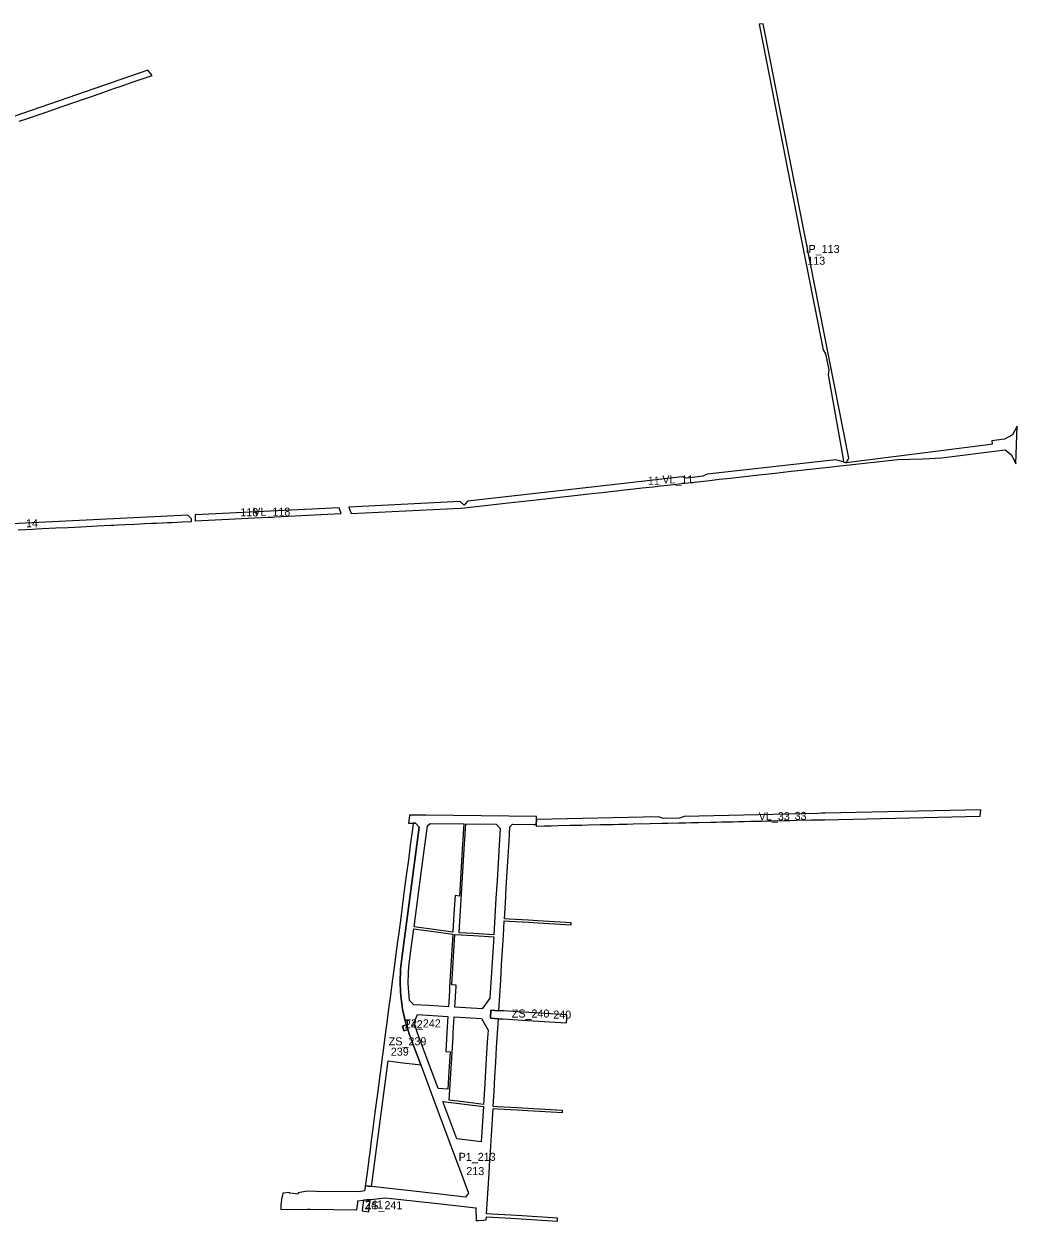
# Model space of a CAD drawing. Extents: x -521939 to -518034, y -1194984 to -1189555.
# Drawn here: x -519897 to -518662, y -1191480 to -1189991 of the extents above; entities that cross this region are included whole.
import ezdxf

# ---------------------------------------------------------------- set-up
doc = ezdxf.new("R2010")
doc.units = 0
doc.layers.add('96120023', color=7, linetype='Continuous')
doc.layers.add('ID VPS', color=7, linetype='Continuous')

msp = doc.modelspace()

# ---------------------------------------------------------------- linework, layer by layer
at = {"layer": '96120023'}
for points in [[(-518977.46, -1189990.66), (-518982.75, -1189991.08)], [(-518982.75, -1189991.08), (-518973.66, -1190037.25)], [(-518968.46, -1190036.36), (-518977.46, -1189990.66)], [(-518973.66, -1190037.25), (-518966.93, -1190071.42)], [(-518961.73, -1190070.59), (-518968.46, -1190036.36)], [(-519742.92, -1190048.01), (-519787.45, -1190063.39), (-519954.51, -1190121.09), (-519959.21, -1190124.83), (-519978.27, -1190131.41), (-519984.27, -1190131.37), (-520061.95, -1190158.2), (-520231.96, -1190216.92), (-520235.61, -1190223.15)], [(-519762.5, -1190063.2), (-519737.67, -1190054.66)], [(-519737.67, -1190054.66), (-519742.92, -1190048.01)], [(-519802.38, -1190076.99), (-519794.41, -1190074.26)], [(-519794.41, -1190074.26), (-519785.22, -1190071.01)], [(-519785.22, -1190071.01), (-519776.17, -1190067.93)], [(-519776.17, -1190067.93), (-519762.5, -1190063.2)], [(-518966.93, -1190071.42), (-518932.65, -1190245.48), (-518903.01, -1190395.98), (-518899.95, -1190401.14), (-518896.05, -1190420.93), (-518896.92, -1190426.87), (-518880.88, -1190515.41), (-518878.11, -1190531.65)], [(-518871.13, -1190530.87), (-518961.73, -1190070.59)], [(-519849.58, -1190093.29), (-519821.87, -1190083.74)], [(-519821.87, -1190083.74), (-519813.04, -1190080.72)], [(-519813.04, -1190080.72), (-519802.38, -1190076.99)], [(-519893.94, -1190108.6), (-519871.89, -1190101.04)], [(-519871.89, -1190101.04), (-519862.6, -1190097.78)], [(-519862.6, -1190097.78), (-519849.58, -1190093.29)], [(-519903.02, -1190111.63), (-519893.94, -1190108.6)], [(-518661.8, -1190490.82), (-518667.64, -1190501.77), (-518677.22, -1190507.17), (-518693.26, -1190509.28)], [(-518663.34, -1190537.95), (-518661.8, -1190490.82)], [(-518693.26, -1190509.28), (-518692.74, -1190513.36), (-518697.59, -1190513.92), (-518874.29, -1190536.33)], [(-518810.26, -1190532.19), (-518779.08, -1190531.51), (-518755.65, -1190530.1), (-518676.76, -1190520.2), (-518668.57, -1190526.63), (-518663.34, -1190537.95)], [(-518887.27, -1190532.68), (-519047.1, -1190550.59), (-519052.5, -1190553.21), (-519072.55, -1190555.45), (-519078.39, -1190554.09), (-519168.97, -1190564.24), (-519345.4, -1190584.01), (-519349.64, -1190589.23)], [(-518884.52, -1190533.45), (-518887.27, -1190532.68)], [(-518877.94, -1190535.3), (-518884.52, -1190533.45)], [(-518878.11, -1190531.65), (-518877.94, -1190535.3)], [(-518877.94, -1190535.3), (-518874.29, -1190536.33)], [(-518874.29, -1190536.33), (-518877.94, -1190535.3)], [(-518877.74, -1190539.66), (-518810.26, -1190532.19)], [(-518874.29, -1190536.33), (-518871.13, -1190530.87)], [(-518983.05, -1190551.46), (-518962.5, -1190549.15)], [(-518962.5, -1190549.15), (-518942.66, -1190546.94)], [(-518942.66, -1190546.94), (-518930.55, -1190545.57)], [(-518930.55, -1190545.57), (-518919.4, -1190544.34)], [(-518919.4, -1190544.34), (-518899.77, -1190542.15)], [(-518899.77, -1190542.15), (-518882.35, -1190540.18)], [(-518882.35, -1190540.18), (-518877.74, -1190539.66)], [(-519114.47, -1190566.26), (-519105.69, -1190565.24)], [(-519105.69, -1190565.24), (-519096.49, -1190564.2)], [(-519096.49, -1190564.2), (-519078.49, -1190562.26)], [(-519078.49, -1190562.26), (-519051.92, -1190559.12)], [(-519051.92, -1190559.12), (-519044.06, -1190558.34)], [(-519044.06, -1190558.34), (-519032.44, -1190556.99)], [(-519032.44, -1190556.99), (-519018.45, -1190555.44)], [(-519018.45, -1190555.44), (-519008.01, -1190554.21)], [(-519008.01, -1190554.21), (-518993.5, -1190552.64)], [(-518993.5, -1190552.64), (-518983.05, -1190551.46)], [(-519244.88, -1190580.73), (-519230.8, -1190579.2)], [(-519230.8, -1190579.2), (-519212.48, -1190577.18)], [(-519212.48, -1190577.18), (-519194.65, -1190575.18)], [(-519194.65, -1190575.18), (-519178.48, -1190573.43)], [(-519178.48, -1190573.43), (-519159.93, -1190571.22)], [(-519159.93, -1190571.22), (-519150.74, -1190570.16)], [(-519150.74, -1190570.16), (-519138.65, -1190568.93)], [(-519138.65, -1190568.93), (-519128.12, -1190567.71)], [(-519128.12, -1190567.71), (-519114.47, -1190566.26)], [(-519505.17, -1190592.27), (-519684.06, -1190601.07)], [(-519502.67, -1190599.7), (-519505.17, -1190592.27)], [(-519354.59, -1190584.65), (-519492.88, -1190591.75)], [(-519492.88, -1190591.75), (-519490.33, -1190599.63)], [(-519490.33, -1190599.63), (-519354.17, -1190593)], [(-519349.64, -1190589.23), (-519354.59, -1190584.65)], [(-519354.17, -1190593), (-519349.34, -1190592.5)], [(-519349.34, -1190592.5), (-519294.71, -1190586.4)], [(-519294.71, -1190586.4), (-519279.13, -1190584.54)], [(-519279.13, -1190584.54), (-519244.88, -1190580.73)], [(-519693.24, -1190601.52), (-519752.34, -1190604.4), (-519929.64, -1190613.04), (-519935.19, -1190615.32), (-519939.78, -1190615.54)], [(-519713.65, -1190610.53), (-519700.36, -1190609.88)], [(-519700.36, -1190609.88), (-519688.65, -1190609.3)], [(-519688.62, -1190605.97), (-519693.24, -1190601.52)], [(-519688.65, -1190609.3), (-519688.62, -1190605.97)], [(-519684.13, -1190608.58), (-519502.67, -1190599.7)], [(-519684.06, -1190601.07), (-519684.13, -1190608.58)], [(-519904.19, -1190619.79), (-519886.32, -1190618.93)], [(-519886.32, -1190618.93), (-519881.51, -1190618.7)], [(-519881.51, -1190618.7), (-519874.3, -1190618.35)], [(-519874.3, -1190618.35), (-519857.39, -1190617.5)], [(-519857.39, -1190617.5), (-519842, -1190616.75)], [(-519842, -1190616.75), (-519826.46, -1190615.97)], [(-519826.46, -1190615.97), (-519806.02, -1190614.98)], [(-519806.02, -1190614.98), (-519789.16, -1190614.2)], [(-519789.16, -1190614.2), (-519785.45, -1190613.97)], [(-519785.45, -1190613.97), (-519780.36, -1190613.76)], [(-519780.36, -1190613.76), (-519770.89, -1190613.31)], [(-519770.89, -1190613.31), (-519759.09, -1190612.73)], [(-519759.09, -1190612.73), (-519746.72, -1190612.13)], [(-519746.72, -1190612.13), (-519738.62, -1190611.73)], [(-519738.62, -1190611.73), (-519732.39, -1190611.44)], [(-519732.39, -1190611.44), (-519725.37, -1190611.1)], [(-519725.37, -1190611.1), (-519719.21, -1190610.77)], [(-519719.21, -1190610.77), (-519713.65, -1190610.53)], [(-519259.67, -1190980.24), (-519259.53, -1190976.44), (-519397.29, -1190974.84), (-519409.21, -1190974.7), (-519417.62, -1190974.6), (-519417.66, -1190974.95), (-519417.58, -1190975.61), (-519417.75, -1190975.6), (-519418.57, -1190981.92), (-519418.92, -1190984.59), (-519412.96, -1190984.66), (-519411.43, -1190984.67), (-519409.91, -1190984.69), (-519405.56, -1190989.71), (-519426.73, -1191149.73), (-519428.73, -1191166.25), (-519429.31, -1191182.88), (-519428.77, -1191193.5), (-519428.47, -1191199.49), (-519426.21, -1191215.98), (-519422.56, -1191232.21)], [(-519259.67, -1190980.24), (-519259.89, -1190986.43)], [(-519259.89, -1190986.43), (-519259.67, -1190980.24)], [(-519210.6, -1190987.17), (-519202.99, -1190986.99), (-519195.39, -1190986.84), (-519180.12, -1190986.51), (-519171.98, -1190986.32), (-519164.58, -1190986.14), (-519157.3, -1190985.98), (-519146.73, -1190985.75), (-519139.45, -1190985.59), (-519118.38, -1190985.11), (-519103.75, -1190984.78), (-519096.18, -1190984.64), (-519082.46, -1190984.32), (-519074.13, -1190984.14), (-519066.62, -1190983.97), (-519057.96, -1190983.78), (-519043.29, -1190983.45), (-519036.25, -1190983.29), (-519029.04, -1190983.14), (-519015.53, -1190982.84), (-519008.2, -1190982.68), (-519001.41, -1190982.5), (-518993.81, -1190982.32), (-518988.21, -1190982.23), (-518979.42, -1190982.05), (-518971.69, -1190981.85), (-518960, -1190981.61), (-518951.6, -1190981.45), (-518943.98, -1190981.24), (-518936.34, -1190981.09), (-518918.12, -1190980.66), (-518905.51, -1190980.41), (-518900.98, -1190980.31), (-518707.73, -1190975.95), (-518706.73, -1190968.01), (-518900.54, -1190972.29), (-518905.06, -1190972.39), (-518909.73, -1190972.5), (-519076.07, -1190976.18), (-519081.68, -1190978.3), (-519101.85, -1190978.75), (-519107.55, -1190976.87), (-519259.67, -1190980.24)], [(-519412.96, -1190984.66), (-519413.94, -1190992.07), (-519416.58, -1191012.09), (-519418.96, -1191030.07), (-519421.56, -1191049.69), (-519424.05, -1191068.52), (-519425.76, -1191081.47), (-519428.51, -1191102.27), (-519430.97, -1191120.9), (-519432.39, -1191131.65), (-519434.43, -1191147.07), (-519436.7, -1191164.25), (-519438.99, -1191181.55), (-519441.23, -1191198.47), (-519443.51, -1191215.75), (-519445.75, -1191232.74), (-519448.07, -1191250.27), (-519450.34, -1191267.46), (-519451.46, -1191275.9), (-519452.43, -1191283.22), (-519454.38, -1191298), (-519457.39, -1191320.76), (-519458.94, -1191332.49), (-519461, -1191348.01), (-519463.15, -1191364.31), (-519465.11, -1191379.15), (-519467.09, -1191394.09), (-519468.15, -1191402.09), (-519468.71, -1191406.36), (-519470.37, -1191418.91), (-519472.32, -1191433.7), (-519472.58, -1191435.69)], [(-519429.31, -1191182.88), (-519428.73, -1191166.25), (-519426.73, -1191149.73), (-519405.56, -1190989.71), (-519409.91, -1190984.69), (-519411.43, -1190984.67), (-519412.96, -1190984.66)], [(-519387.1, -1191117.04), (-519405.94, -1191114.55), (-519411.89, -1191113.76), (-519408.9, -1191091.16), (-519405.91, -1191068.61), (-519403.03, -1191046.8), (-519400.14, -1191024.99), (-519397.25, -1191003.18), (-519395.22, -1190987.84), (-519391.87, -1190984.9), (-519349.98, -1190985.39), (-519350.34, -1190991.38), (-519351.18, -1191005.37), (-519351.49, -1191010.37), (-519355.39, -1191075.29), (-519360.86, -1191074.57), (-519362.23, -1191097.34), (-519363.6, -1191120.15), (-519387.1, -1191117.04)], [(-519337.67, -1191121.99), (-519355.64, -1191120.91), (-519348.98, -1191010.4), (-519348.68, -1191005.4), (-519347.84, -1190991.41), (-519347.48, -1190985.42), (-519309.96, -1190985.85), (-519304.76, -1190991.38), (-519306.01, -1191012.14), (-519307.33, -1191034.1), (-519308.65, -1191056.06), (-519309.98, -1191078.02), (-519311.34, -1191100.73), (-519312.71, -1191123.49), (-519318.7, -1191123.13), (-519337.67, -1191121.99)], [(-519306.37, -1191217.84), (-519305.23, -1191198.83), (-519304.09, -1191179.86), (-519302.94, -1191160.9), (-519301.84, -1191142.63), (-519300.74, -1191124.36), (-519299.64, -1191106.09), (-519293.65, -1191106.46), (-519269.7, -1191107.9), (-519258.03, -1191108.6), (-519216.41, -1191111.11), (-519216.29, -1191108.61), (-519257.89, -1191106.1), (-519269.55, -1191105.4), (-519293.5, -1191103.96), (-519299.49, -1191103.6), (-519298.32, -1191084.03), (-519297.14, -1191064.57), (-519295.97, -1191045.1), (-519294.83, -1191026.14), (-519293.69, -1191007.17), (-519292.6, -1190989.16), (-519289.31, -1190986.09), (-519262.38, -1190986.4), (-519259.89, -1190986.43)], [(-519259.89, -1190986.43), (-519259.96, -1190988.33)], [(-519259.96, -1190988.33), (-519250.24, -1190988.04)], [(-519250.24, -1190988.04), (-519241.28, -1190987.85)], [(-519241.28, -1190987.85), (-519232.69, -1190987.61), (-519218.24, -1190987.34), (-519210.6, -1190987.17)], [(-519387.43, -1191119.47), (-519363.75, -1191122.6), (-519367.7, -1191188.1), (-519368, -1191193.09), (-519368.84, -1191207.07), (-519369.2, -1191213.06), (-519393.15, -1191211.62), (-519412.25, -1191210.47), (-519417.68, -1191205.18), (-519419.26, -1191184.09), (-519418.72, -1191170.93), (-519418.4, -1191162.95), (-519415.36, -1191139.98), (-519412.21, -1191116.19), (-519406.26, -1191116.98), (-519387.43, -1191119.47)], [(-519359.71, -1191188.58), (-519359.57, -1191186.24), (-519365.06, -1191185.91), (-519361.27, -1191123.02), (-519337.82, -1191124.43), (-519318.85, -1191125.58), (-519312.86, -1191125.94), (-519314.75, -1191157.38), (-519316.65, -1191188.82), (-519317.45, -1191202.15), (-519327.17, -1191215.59), (-519361.21, -1191213.54), (-519360.85, -1191207.55), (-519360.01, -1191193.57), (-519359.71, -1191188.58)], [(-519428.77, -1191193.5), (-519429.31, -1191182.88)], [(-519428.47, -1191199.49), (-519428.77, -1191193.5)], [(-519422.56, -1191232.21), (-519426.21, -1191215.98), (-519428.47, -1191199.49)], [(-519316.35, -1191217.24), (-519316.95, -1191227.22)], [(-519316.95, -1191227.22), (-519316.35, -1191217.24)], [(-519306.37, -1191217.84), (-519316.35, -1191217.24)], [(-519316.35, -1191217.24), (-519306.37, -1191217.84)], [(-519276.43, -1191219.64), (-519300.38, -1191218.2), (-519306.37, -1191217.84)], [(-519221.65, -1191222.94), (-519269, -1191220.09), (-519276.43, -1191219.64)], [(-519466.53, -1191452.71), (-519465.48, -1191452.58), (-519448.03, -1191450.51), (-519432.28, -1191452.28), (-519402.01, -1191455.67), (-519374.98, -1191458.69), (-519335.08, -1191463.16), (-519334.48, -1191479.02), (-519333.28, -1191478.93), (-519332.56, -1191478.87), (-519331.7, -1191478.8), (-519325.22, -1191478.24), (-519322.03, -1191477.97), (-519321.8, -1191474.15), (-519291.33, -1191476), (-519233.67, -1191479.5), (-519233.5, -1191475.79), (-519277.54, -1191473.14), (-519291.64, -1191472.29), (-519315.59, -1191470.85), (-519321.58, -1191470.48), (-519320.82, -1191457.76), (-519320.06, -1191445.13), (-519318.53, -1191419.83), (-519317.5, -1191402.75), (-519316.93, -1191393.15), (-519315.32, -1191366.47), (-519313.69, -1191339.37), (-519307.7, -1191339.73), (-519283.74, -1191341.17), (-519270.52, -1191341.97), (-519227.35, -1191344.57), (-519227.23, -1191342.07), (-519270.38, -1191339.47), (-519283.59, -1191338.68), (-519307.55, -1191337.24), (-519313.54, -1191336.88), (-519312.43, -1191318.46), (-519311.32, -1191300.09), (-519310.22, -1191281.73), (-519309.14, -1191263.76), (-519308.05, -1191245.79), (-519306.97, -1191227.82), (-519316.95, -1191227.22)], [(-519421.48, -1191235.61), (-519426.25, -1191237.12), (-519424.56, -1191242.44), (-519424.44, -1191242.84), (-519421.98, -1191242.06), (-519419.67, -1191241.33)], [(-519424.44, -1191242.84), (-519424.56, -1191242.44), (-519426.25, -1191237.12), (-519421.48, -1191235.61)], [(-519422.56, -1191232.21), (-519421.48, -1191235.61)], [(-519421.48, -1191235.61), (-519422.56, -1191232.21)], [(-519421.46, -1191235.67), (-519421.48, -1191235.61)], [(-519421.48, -1191235.61), (-519421.46, -1191235.67)], [(-519420.1, -1191239.99), (-519421.46, -1191235.67)], [(-519421.46, -1191235.67), (-519420.1, -1191239.99)], [(-519368.53, -1191293.54), (-519369.85, -1191315.4), (-519381.99, -1191314.67), (-519399.84, -1191266.86), (-519408.14, -1191244.64), (-519411.75, -1191232.59), (-519407.56, -1191222.77), (-519369.92, -1191225.04), (-519371.12, -1191245), (-519372.54, -1191268.51), (-519367.05, -1191268.84), (-519368.53, -1191293.54)], [(-519350.27, -1191331.3), (-519368.17, -1191329.12), (-519363.44, -1191250.47), (-519363.14, -1191245.48), (-519361.93, -1191225.52), (-519327.89, -1191227.57), (-519319.85, -1191242.08), (-519320.75, -1191257), (-519322.43, -1191284.95), (-519323.85, -1191308.41), (-519325.41, -1191334.34), (-519350.27, -1191331.3)], [(-519316.95, -1191227.22), (-519306.97, -1191227.82)], [(-519306.97, -1191227.82), (-519300.98, -1191228.18), (-519277.03, -1191229.63)], [(-519277.03, -1191229.63), (-519270.66, -1191230.01)], [(-519270.66, -1191230.01), (-519222.12, -1191232.93), (-519221.9, -1191228.24), (-519221.65, -1191222.94)], [(-519419.67, -1191241.33), (-519417.54, -1191248.08), (-519403.63, -1191285.31), (-519387.2, -1191329.32), (-519369.81, -1191375.88), (-519355.34, -1191414.63), (-519344.11, -1191444.69), (-519347.98, -1191449.64), (-519386.94, -1191445.28), (-519412.78, -1191442.38), (-519438.52, -1191439.5), (-519464.69, -1191436.57), (-519468.64, -1191436.13), (-519472.58, -1191435.69), (-519472.77, -1191437.09), (-519473.18, -1191440.03), (-519473.41, -1191441.72), (-519480.3, -1191443.11), (-519533.77, -1191442.8), (-519544.94, -1191442.33), (-519556.21, -1191444.23), (-519556.39, -1191445.91), (-519562.18, -1191445.17), (-519566.72, -1191444.78), (-519566.62, -1191443.98), (-519575.16, -1191444.67), (-519576.66, -1191452.79), (-519577.4, -1191456.82), (-519577.64, -1191459.18), (-519577.51, -1191465.05), (-519544.61, -1191464.84), (-519540.95, -1191464.89), (-519483.25, -1191465.69), (-519481.98, -1191456.8), (-519481.78, -1191454.44), (-519474.91, -1191453.7)], [(-519419.67, -1191241.33), (-519421.98, -1191242.06), (-519424.44, -1191242.84)], [(-519419.67, -1191241.33), (-519420.1, -1191239.99)], [(-519420.1, -1191239.99), (-519419.67, -1191241.33)], [(-519417.54, -1191248.08), (-519419.67, -1191241.33)], [(-519403.63, -1191285.31), (-519417.54, -1191248.08)], [(-519461.41, -1191411.78), (-519444.02, -1191280.38), (-519431.59, -1191281.9)], [(-519431.59, -1191281.9), (-519426, -1191282.58), (-519410.34, -1191284.49), (-519403.63, -1191285.31)], [(-519328.22, -1191381.04), (-519358.62, -1191377.27), (-519376.01, -1191330.68), (-519325.56, -1191336.84), (-519328.22, -1191381.04)], [(-519464.69, -1191436.57), (-519463.91, -1191430.62), (-519461.41, -1191411.78)], [(-519472.58, -1191435.69), (-519468.64, -1191436.13), (-519464.69, -1191436.57)], [(-519474.91, -1191453.7), (-519475.89, -1191462.49), (-519476.39, -1191466.96), (-519468.24, -1191467.91)], [(-519466.53, -1191452.71), (-519474.91, -1191453.7)], [(-519474.91, -1191453.7), (-519466.53, -1191452.71)], [(-519467.73, -1191463.4), (-519466.53, -1191452.71)], [(-519468.24, -1191467.91), (-519467.73, -1191463.4)]]:
    msp.add_lwpolyline(points, dxfattribs=at)

# ---------------------------------------------------------------- texts
for s, rotation, p in [('IP_113', 0, (-518924.89, -1190275.57)), ('VL_11', 360, (-519103.07, -1190562.1)), ('VL_118', 0, (-519611.93, -1190602.29)), ('VL_33', 0, (-518983.2, -1190981.04)), ('ZS_240', 0, (-519290.35, -1191226.39)), ('T2_242', 0, (-519424.01, -1191238.65)), ('ZS_239', 0, (-519443.43, -1191260.96)), ('P1_213', 360, (-519356.47, -1191404.63)), ('ZS_241', 0, (-519473.28, -1191464.82))]:
    msp.add_text(s, height=10, rotation=rotation, dxfattribs=at).set_placement(p)
at = {"layer": 'ID VPS'}
for s, rotation, p in [('113', 0, (-518922.78, -1190290.13)), ('11', 0, (-519121.11, -1190563.76)), ('118', 0, (-519627.98, -1190603.04)), ('14', 360, (-519894.57, -1190616.65)), ('33', 360, (-518938.54, -1190980.6)), ('240', 0, (-519238.71, -1191227.75)), ('242', 360, (-519423.47, -1191239.72)), ('239', 0, (-519440.81, -1191273.86)), ('213', 360, (-519346.9, -1191422.34)), ('241', 0, (-519472.78, -1191463.93))]:
    msp.add_text(s, height=10, rotation=rotation, dxfattribs=at).set_placement(p)

doc.saveas('drawing.dxf')
